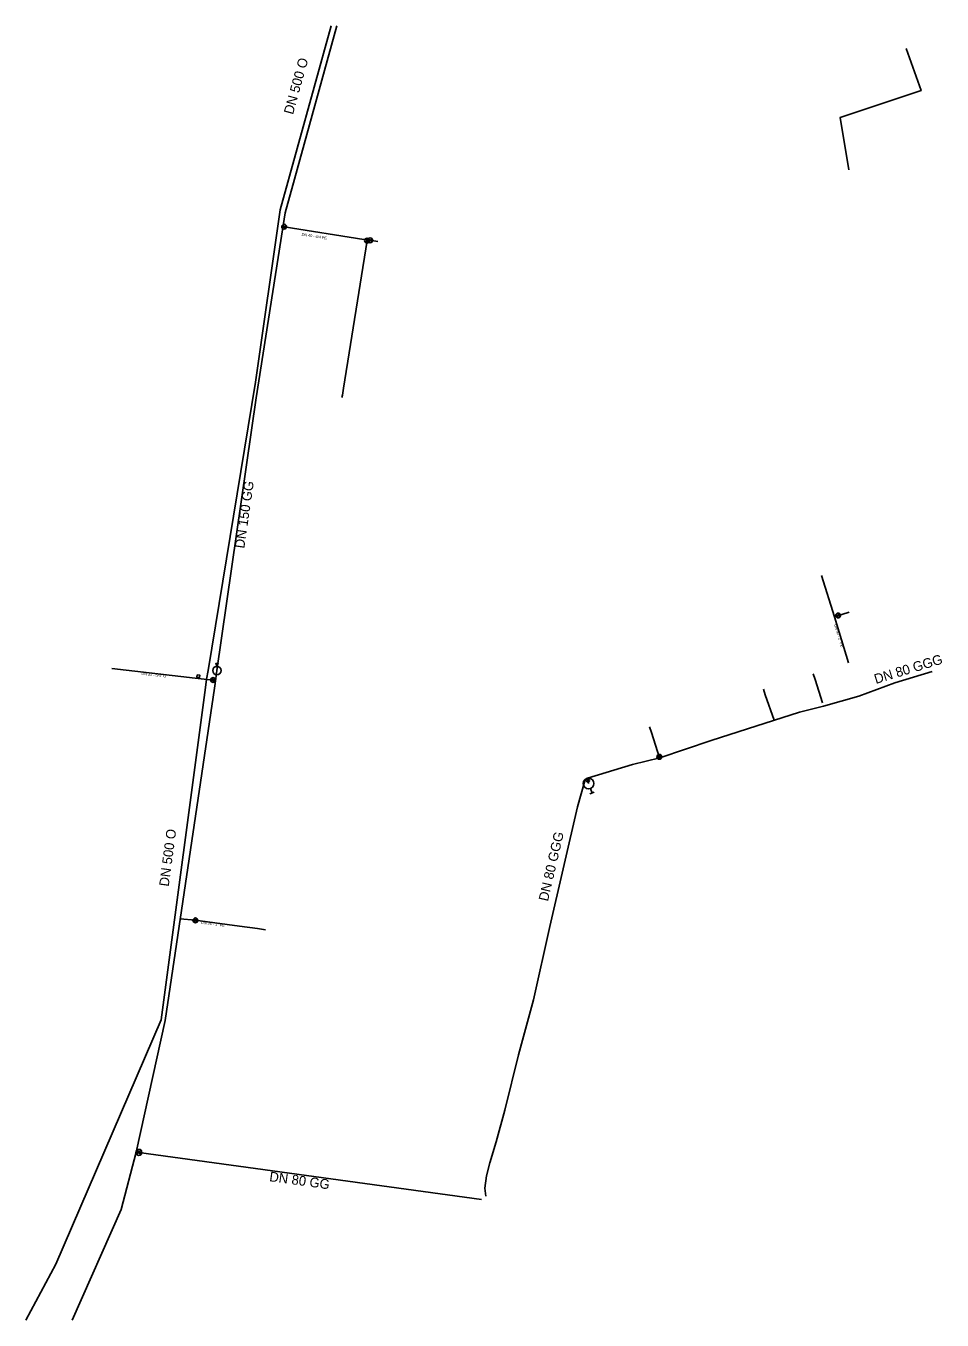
# Model space of a CAD drawing. Extents: x -444543 to -444391, y -1121207 to -1120993.
import ezdxf

# ---------------------------------------------------------------- set-up
doc = ezdxf.new("R2010")
doc.units = 0
for name, color, linetype in [('_hydrantova_odbocka_', 7, 'Continuous'), ('_pripojka_priblizne_', 7, 'Continuous'), ('_voda_smvak_prevzato_z_dokumentace_', 7, 'Continuous'), ('Default', 7, 'Continuous'), ('MoLevel 27', 7, 'Continuous'), ('MoLevel 28', 7, 'Continuous'), ('MoLevel 30', 7, 'Continuous'), ('MoLevel 32', 7, 'Continuous'), ('MoLevel 42', 7, 'Continuous'), ('MoLevel 46', 7, 'Continuous'), ('MoLevel 53', 7, 'Continuous')]:
    doc.layers.add(name, color=color, linetype=linetype)

# ---------------------------------------------------------------- blocks, each defined once
blk = doc.blocks.new('_uzaver_')
at = {"layer": 'Default'}
for p, q in [((-0.000035, -0.000035), (0.000035, 0.000035)), ((0.000035, -0.000035), (-0.000035, 0.000035))]:
    blk.add_line(p, q, dxfattribs=at)
for radius in [0.00005, 0.0000025]:
    blk.add_circle((0, 0), radius, dxfattribs=at)
blk = doc.blocks.new('_uzaver_pripojka_')
at = {"layer": 'Default'}
for p, q in [((-0.000035, -0.000035), (0.000035, 0.000035)), ((0.000035, -0.000035), (-0.000035, 0.000035))]:
    blk.add_line(p, q, dxfattribs=at)
for radius in [0.00005, 0.0000025]:
    blk.add_circle((0, 0), radius, dxfattribs=at)
blk = doc.blocks.new('_hydrant_voda_')
at = {"layer": 'Default'}
for p, q in [((-0.000023, 0.000095), (0.000023, 0.000095)), ((0, 0.000095), (0, 0.00005))]:
    blk.add_line(p, q, dxfattribs=at)
blk.add_circle((0, 0), 0.00005, dxfattribs=at)
blk = doc.blocks.new('_sachta_voda_')
at = {"layer": 'Default'}
blk.add_lwpolyline([(-0.00001, 0.000065), (0, 0.000035), (0.00001, 0.000065)], dxfattribs=at)
blk.add_circle((0, 0), 0.000035, dxfattribs=at)
blk = doc.blocks.new('_poklop_voda_')
at = {"layer": 'Default'}
blk.add_lwpolyline([(-0.00002, 0.00002), (0.00002, 0.00002), (0.00002, -0.00002), (-0.00002, -0.00002), (-0.00002, 0.00002)], dxfattribs=at)

msp = doc.modelspace()

# ---------------------------------------------------------------- linework, layer by layer
at = {"layer": '_hydrantova_odbocka_'}
msp.add_line((-444449.8, -1121118.54), (-444449.98, -1121117.65), dxfattribs=at)
at = {"layer": '_pripojka_priblizne_'}
for p, q in [((-444500.32, -1121026.49), (-444500.12, -1121026.53)), ((-444409.16, -1121090.97), (-444411.28, -1121084.18)), ((-444409.16, -1121090.97), (-444406.71, -1121090.24)), ((-444406.83, -1121098.6), (-444409.16, -1121090.97)), ((-444514.81, -1121101.11), (-444528.61, -1121099.56))]:
    msp.add_line(p, q, dxfattribs=at)
for points in [[(-444397.31, -1120997.07), (-444394.84, -1121004.04), (-444408.22, -1121008.48), (-444406.8, -1121017.14)], [(-444500.12, -1121026.53), (-444486.97, -1121028.66), (-444486.36, -1121028.69)], [(-444486.36, -1121028.69), (-444486.42, -1121028.82), (-444490.32, -1121053.22), (-444490.5, -1121054.34), (-444490.57, -1121054.75)], [(-444486.36, -1121028.69), (-444485.91, -1121028.78), (-444485.6, -1121028.83), (-444484.61, -1121028.98)], [(-444411.16, -1121105.2), (-444412.37, -1121101.35), (-444412.67, -1121100.4)], [(-444511.45, -1121101.49), (-444512.33, -1121101.39), (-444514.81, -1121101.11)], [(-444419.15, -1121108.09), (-444420.59, -1121103.9), (-444420.91, -1121102.95)], [(-444438.06, -1121114.29), (-444439.42, -1121110.13), (-444439.73, -1121109.18)], [(-444517.29, -1121140.91), (-444514.81, -1121141.15), (-444507.49, -1121142.1)], [(-444507.49, -1121142.1), (-444504.52, -1121142.49), (-444503.18, -1121142.7)]]:
    msp.add_lwpolyline(points, dxfattribs=at)
at = {"layer": '_voda_smvak_prevzato_z_dokumentace_'}
for p, q in [((-444491.4, -1120993.34), (-444498.43, -1121018.67)), ((-444524.56, -1121179.44), (-444524.13, -1121179.51)), ((-444524.13, -1121179.51), (-444467.52, -1121187.31))]:
    msp.add_line(p, q, dxfattribs=at)
for points in [[(-444492.35, -1120993.34), (-444500.77, -1121023.72), (-444504.83, -1121052.19), (-444512.7, -1121099.84)], [(-444498.43, -1121018.67), (-444499.97, -1121024.21), (-444504.74, -1121054.83), (-444511.22, -1121099.88)], [(-444512.7, -1121099.84), (-444512.94, -1121101.3), (-444513.12, -1121102.65)], [(-444511.22, -1121099.88), (-444511.41, -1121101.19), (-444511.65, -1121102.79)], [(-444449.96, -1121117.64), (-444442.55, -1121115.4), (-444438.05, -1121114.29), (-444429.56, -1121111.42), (-444423.52, -1121109.48), (-444414.95, -1121106.76), (-444410.99, -1121105.76), (-444405.14, -1121104.09), (-444399.2, -1121101.92), (-444392.99, -1121100.01)], [(-444513.12, -1121102.65), (-444520.46, -1121157.59), (-444537.88, -1121198), (-444542.81, -1121207.22)], [(-444511.65, -1121102.79), (-444519.77, -1121157.68), (-444524.56, -1121179.44)], [(-444466.78, -1121186.71), (-444466.95, -1121185.43), (-444466.66, -1121183.39), (-444466.13, -1121181.23), (-444465.07, -1121177.78), (-444463.64, -1121172.55), (-444461.36, -1121163.39), (-444458.9, -1121154.31), (-444456.23, -1121142.16), (-444451.64, -1121122.4), (-444450.4, -1121118.09), (-444450.2, -1121117.77), (-444449.96, -1121117.64)], [(-444524.56, -1121179.44), (-444527.06, -1121188.95), (-444535.14, -1121207.22)]]:
    msp.add_lwpolyline(points, dxfattribs=at)

# ---------------------------------------------------------------- block references
at = {"layer": 'MoLevel 27'}
for p, xscale, yscale, rotation in [((-444449.9, -1121118.05), 4999.999999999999, 4999.999999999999, -76.91126721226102), ((-444524.13, -1121179.51), 10000, 9999.999999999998, -6.910705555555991)]:
    msp.add_blockref('_uzaver_', p, dxfattribs=dict(at, xscale=xscale, yscale=yscale, rotation=rotation))
at = {"layer": 'MoLevel 28', "xscale": 17636.684303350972, "yscale": 17636.684303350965, "rotation": -160.24735110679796}
msp.add_blockref('_hydrant_voda_', (-444449.8, -1121118.54), dxfattribs=at)
at = {"layer": 'MoLevel 30', "xscale": 20000, "yscale": 20000}
msp.add_blockref('_sachta_voda_', (-444511.22, -1121099.88), dxfattribs=at)
at = {"layer": 'MoLevel 42', "xscale": 10000, "yscale": 10000.000000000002, "rotation": -7.933271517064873}
msp.add_blockref('_poklop_voda_', (-444514.3, -1121100.8), dxfattribs=at)
at = {"layer": 'MoLevel 53'}
for p, xscale, yscale, rotation in [((-444500.12, -1121026.53), 7999.999999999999, 7999.999999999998, -9.22114854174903), ((-444408.56, -1121090.78), 7999.999999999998, 8000, 17.592425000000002), ((-444511.87, -1121101.44), 8000, 7999.999999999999, -8.544593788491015), ((-444438.11, -1121114.13), 7999.999999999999, 8000.000000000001, -71.94893611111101), ((-444514.79, -1121141.16), 8000, 8000, -7.31269810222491)]:
    msp.add_blockref('_uzaver_pripojka_', p, dxfattribs=dict(at, xscale=xscale, yscale=yscale, rotation=rotation))
at = {"layer": 'MoLevel 53', "xscale": 7999.999999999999, "yscale": 7999.999999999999}
for p in [(-444486.42, -1121028.82), (-444485.91, -1121028.78)]:
    msp.add_blockref('_uzaver_pripojka_', p, dxfattribs=at)

# ---------------------------------------------------------------- texts
at = {"layer": 'MoLevel 32'}
for s, rotation, p in [('DN 40 - 6/4 PE', 350.7789, (-444497.26, -1121027.98)), ("DN 50 - 2'' PE", 287.0107, (-444409.23, -1121092.3)), ("DN 32 - 5/4'' O", 353.5761, (-444523.72, -1121100.57)), ("DN 25 - 1'' PE", 352.5876, (-444513.86, -1121141.73))]:
    msp.add_text(s, height=0.455, rotation=rotation, dxfattribs=at).set_placement(p)
at = {"layer": 'MoLevel 46'}
for s, rotation, p in [('DN 500 O', 74.5115, (-444498.66, -1121008.08)), ('DN 150 GG', 81.8198, (-444506.71, -1121079.76)), ('DN 80 GGG', 17.0595, (-444402.31, -1121102.1)), ('DN 500 O', 82.3874, (-444519.2, -1121135.63)), ('DN 80 GGG', 76.9228, (-444456.52, -1121138.1)), ('DN 80 GG', 352.1549, (-444502.63, -1121184.25))]:
    msp.add_text(s, height=1.605, rotation=rotation, dxfattribs=at).set_placement(p)

doc.saveas('drawing.dxf')
